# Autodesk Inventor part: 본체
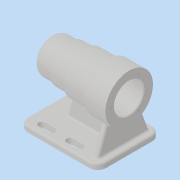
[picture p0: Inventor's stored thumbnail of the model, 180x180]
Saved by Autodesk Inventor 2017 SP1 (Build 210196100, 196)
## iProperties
Part Number: 본체
Material: 일반
Document SubType Name: Modeling
Designer: MRC
Density: 1 g/cm^3
Appearance: 기본값
Author: MRC
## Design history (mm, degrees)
sketch "스케치1"
  geometry: L1 (0, 0)-(-112, 0); L2 (-112, 0)-(-112, 25); L3 (-112, 25)-(-88, 25); L4 (-88, 25)-(-88, 27); L5 (-88, 27)-(-66, 27); L6 (-66, 27)-(-66, 30); L7 (-66, 30)-(-32, 30); L8 (-32, 30)-(-32, 34); L9 (-32, 34)-(0, 34); L10 (0, 34)-(0, 21); L11 (0, 21)-(-15, 21); L12 (-15, 21)-(-15, 24); L13 (-15, 24)-(-69, 24); L14 (-69, 24)-(-69, 21); L15 (-69, 21)-(-81, 21); L16 (-81, 21)-(-81, 17.5); L17 (-81, 17.5)-(-99, 17.5); L18 (-99, 17.5)-(-99, 16); L19 (-99, 16)-(-103, 16); L20 (-103, 16)-(-103, 10.5); L21 (-103, 10.5)-(-106, 10.5); L22 (-106, 10.5)-(-106, 0); 1 further point
  constraints: 44 end point, 19 perpendicular, 2 horizontal, 1 coincident, 1 collinear, 1 point on line, 1 vertical, 1 vertical alignment
  dimensions: "d0" = 112 distance of L1.start L1.end; "d1" = 50 diameter of L3 L1; "d2" = 54 diameter of L5 L1; "d3" = 60 diameter of L7 L1; "d4" = 68 diameter of L9 L1; "d6" = 42 diameter of L11 L1; "d7" = 48 diameter of L13 L1; "d8" = 35 diameter of L17 L1; "d9" = 32 diameter of L19 L1; "d10" = 21 diameter of L21 L1; "d11" = 15 distance of L10.end L11.end; "d12" = 54 distance of L12.end L13.end; "d13" = 12 distance of L14.end L15.end; "d14" = 18 distance of L16.end L17.end; "d15" = 4 distance of L18.end L19.end; "d16" = 3 distance of L20.end L21.end; "d17" = 24 distance of L2.end L3.end; "d18" = 46 distance between parallel lines of L6 L2; "d19" = 80 distance between parallel lines of L8 L2
revolve "회전1" sketch "스케치1" stored, may be unused: angle "d20" = 90 deg
fillet "모깎기1" dims "d21" = 8
fillet "모깎기2" dims "d22" = 3
fillet "모깎기3" dims "d23" = 3
chamfer "모따기1" distance "d24" = 1; stored, may be unused: second distance "d25" = 2, angle "d26" = 45 deg
fillet "모깎기4" dims "d27" = 0.3
fillet "모깎기5" dims "d28" = 3
fillet "모깎기6" dims "d29" = 3
sketch "스케치2"
  geometry: L1 (-112, -62)-(0, -62); L2 (0, -62)-(0, -70); L3 (0, -70)-(-112, -70); L4 (-112, -70)-(-112, -62); 1 further point
  constraints: 8 end point, 2 parallel, 1 horizontal, 1 perpendicular, 1 vertical alignment
  dimensions: "d30" = 112 distance of L2.end L3.end; "d31" = 8 distance of L1.end L2.end; "d32" = 70 distance from line of L3 point (0, 0)
extrude "돌출1" join sketch "스케치2" stored distance "d33" = 90; taper "d34" = 0 deg
fillet "모깎기7" dims "d35" = 12
sketch "스케치3"
  geometry: L1 (100, 12)-(100, 78) reference; L2 (84, 49)-(92, 49); L3 (92, 49)-(92, 41); L4 (92, 41)-(84, 41); L5 (84, 41)-(84, 49); L6 (84, 49)-(92, 41); L7 (92, 49)-(84, 41); 4 further points
  constraints: 12 end point, 4 midpoint, 2 parallel, 1 horizontal, 1 horizontal alignment, 1 perpendicular
  dimensions: "d36" = 8 distance of L3.end L4.end; "d37" = 8 distance of L2.end L3.end; "d38" = 8 distance between parallel lines of L1 L3
extrude "돌출2" join sketch "스케치3" stored distance "d39" = 0; taper "d40" = 0 deg
sketch "스케치4"
  geometry: L1 (-85, -62)-(-78.072, -36.145); L2 (-100, -62)-(-12, -62) reference; L3 (0, -62)-(0, -70) reference; 1 further point
  constraints: 2 end point, 1 point on line
  dimensions: "d41" = 105 deg angle of L1 L2; "d42" = 85 distance from line of L1.start L3
feature "리브1" sketch "스케치4" dims "d43" = 1, "d44" = 8, "d45" = 0, "d46" = 0, "d47" = 1, "d48" = 1
sketch "스케치5"
  geometry: L1 (29.05, 32.832)-(41, 0); L2 (37, 0)-(49, 0) reference; L3 (49, -8)-(49, 0) reference
  constraints: 2 end point, 1 point on line
  dimensions: "d49" = 8 distance from line of L1.end L3; "d51" = 110 deg angle of L1 L2
feature "리브2" sketch "스케치5" dims "d52" = 1, "d53" = 8, "d54" = 0, "d55" = 0, "d56" = 1, "d57" = 1
sketch "스케치6"
  geometry: L1 (-12, -12)-(-12, -78) reference; L2 (8, -78)-(23, -78); L3 (8, -82.5)-(23, -82.5); L4 (23, -73.5)-(8, -73.5); A1 r 4.5 centre (8, -78) between (8, -73.5) and (8, -82.5); A2 r 4.5 centre (23, -78) between (23, -82.5) and (23, -73.5); 2 further points
  constraints: 8 end point, 4 point on circle, 4 tangent, 2 centre point, 1 horizontal, 1 midpoint, 1 parallel
  dimensions: "d58" = 15 distance of L2.start L2.end; "d59" = 9 distance between parallel lines of L3 L4; "d60" = 33 distance from line of L2 point (100, -45); "d61" = 20 distance from line of L2.start L1
extrude "돌출3" cut sketch "스케치6" stored distance "d62" = 90; taper "d63" = 0 deg
fillet "모깎기8" dims "d70" = 3
fillet "모깎기9" dims "d71" = 3
sketch "스케치7"
  geometry: C1 r 22 at (0, 0) reference; 1 further point
  constraints: 1 horizontal alignment
  dimensions: "d72" = 26 distance of point (-26, 0) C1.centre
hole "구멍1" sketch "스케치7" at (-26, 0) diameter "d73" = 3.242; stored, may be unused: countersink angle "d77" = 90 deg, drill point angle "d79" = 118 deg; dims "d74" = 8, "d75" = 4, "d76" = 2, "d78" = 11
node "솔리드1"
mirror "미러1"
pattern_linear "직사각형 패턴1" dims "d66" = 40, "d69" = 66
pattern_circular "원형 패턴1" dims angle "d81" = 360 deg
